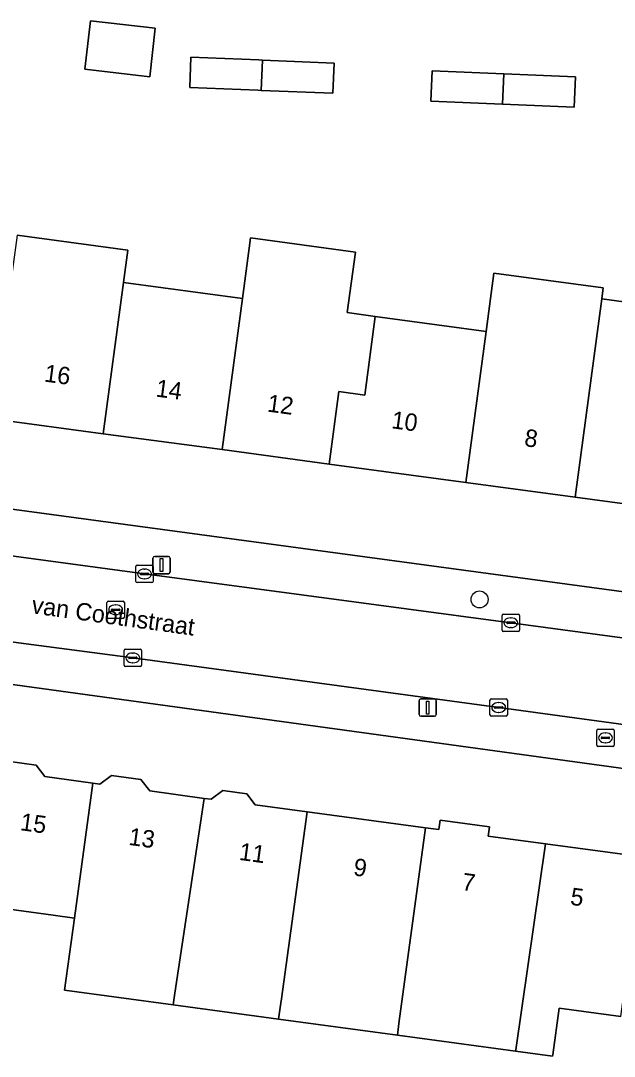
# Model space of a CAD drawing. Extents: x 161258 to 161838, y 380833 to 381727.
# Drawn here: x 161656.1 to 161690.3, y 381559.4 to 381619 of the extents above; entities that cross this region are included whole.
import ezdxf

# ---------------------------------------------------------------- set-up
doc = ezdxf.new("R2010")
doc.units = 0
for name, color, linetype in [('IMGEO_Boom', 7, 'Continuous'), ('IMGEO_Brandkraan', 7, 'Continuous'), ('IMGEO_Erf', 7, 'Continuous'), ('IMGEO_Kolk', 7, 'Continuous'), ('IMGEO_Lichtmast', 7, 'Continuous'), ('IMGEO_Openbare_ruimte_label', 7, 'Continuous'), ('IMGEO_Pand', 7, 'Continuous'), ('IMGEO_Pand_nummerreeks', 7, 'Continuous'), ('IMGEO_Rijbaan_lokaal_open', 7, 'Continuous'), ('IMGEO_Rioolput', 7, 'Continuous'), ('IMGEO_Voetpad_open', 7, 'Continuous')]:
    doc.layers.add(name, color=color, linetype=linetype)

msp = doc.modelspace()

# ---------------------------------------------------------------- linework, layer by layer
at = {"layer": 'IMGEO_Boom'}
msp.add_circle((161682.565, 381585.699), 0.489, dxfattribs=at)
at = {"layer": 'IMGEO_Brandkraan'}
for p, q in [((161689.314, 381577.311), (161689.314, 381578.163)), ((161689.389, 381578.237), (161690.241, 381578.237)), ((161689.573, 381577.731), (161689.573, 381577.743)), ((161689.616, 381577.78), (161690.014, 381577.78)), ((161689.802, 381578.017), (161689.827, 381578.017)), ((161690.057, 381577.743), (161690.057, 381577.731)), ((161690.315, 381578.163), (161690.315, 381577.311)), ((161690.241, 381577.237), (161689.389, 381577.237)), ((161690.011, 381577.694), (161689.613, 381577.694)), ((161689.825, 381577.457), (161689.8, 381577.457))]:
    msp.add_line(p, q, dxfattribs=at)
for points in [[(161689.314, 381577.311), (161689.314, 381578.163)], [(161689.389, 381578.237), (161690.241, 381578.237)], [(161690.315, 381578.163), (161690.315, 381577.311)], [(161690.241, 381577.237), (161689.389, 381577.237)]]:
    msp.add_lwpolyline(points, dxfattribs=at)
for centre, radius, start, end in [((161689.391, 381578.161), 0.0765, 91.55205, 178.44795), ((161689.391, 381578.161), 0.0765, 91.55205, 178.44795), ((161689.613, 381577.74), 0.0403, 85.87752, 175.75265), ((161689.61, 381577.73), 0.0366, 178.93798, 274.71019), ((161690.014, 381577.737), 0.043, 264.86636, 352.45326), ((161690.018, 381577.742), 0.0386, 1.73085, 96.63898), ((161690.239, 381578.161), 0.0765, 1.55205, 88.44795), ((161690.239, 381578.161), 0.0765, 1.55205, 88.44795), ((161689.391, 381577.313), 0.0765, 181.55205, 268.44795), ((161689.391, 381577.313), 0.0765, 181.55205, 268.44795), ((161690.239, 381577.313), 0.0765, 271.55205, 358.44795), ((161690.239, 381577.313), 0.0765, 271.55205, 358.44795)]:
    msp.add_arc(centre, radius, start, end, dxfattribs=at)
for centre, major_axis, ratio, start_param, end_param in [((161689.801, 381577.737), (-0.387, 0.002), 0.722429, 4.712389, 7.853982), ((161689.826, 381577.737), (-0.39, 0.002), 0.717154, 1.570796, 4.712389)]:
    msp.add_ellipse(centre, major_axis=major_axis, ratio=ratio, start_param=start_param, end_param=end_param, dxfattribs=at)
at = {"layer": 'IMGEO_Erf'}
for points in [[(161659.833, 381616.199), (161660.152, 381618.996), (161663.887, 381618.569), (161663.568, 381615.772)], [(161665.871, 381615.157), (161665.942, 381616.902), (161669.857, 381616.741), (161670.067, 381616.733), (161674.192, 381616.563), (161674.12, 381614.818), (161669.995, 381614.987), (161669.785, 381614.996)], [(161679.831, 381616.104), (161683.955, 381615.935), (161688.08, 381615.765), (161688.009, 381614.02), (161683.883, 381614.19), (161679.759, 381614.359)], [(161681.773, 381592.431), (161673.908, 381593.488), (161667.735, 381594.317), (161660.894, 381595.236), (161654.633, 381596.076), (161647.661, 381597.013), (161641.376, 381597.857), (161634.504, 381598.78), (161627.101, 381599.774), (161615.784, 381601.294), (161615.118, 381596.359), (161707.085, 381583.95), (161707.511, 381583.893), (161708.709, 381583.729), (161709.752, 381591.347), (161708.256, 381591.548), (161707.903, 381588.922), (161701.922, 381589.725), (161695.354, 381590.607), (161688.066, 381591.586)]]:
    msp.add_lwpolyline(points, close=True, dxfattribs=at)
for points in [[(161655.925, 381606.655), (161662.313, 381605.797), (161662.062, 381603.929), (161668.903, 381603.01), (161669.293, 381605.911), (161669.371, 381606.495), (161675.411, 381605.684), (161674.943, 381602.199), (161676.556, 381601.982), (161682.941, 381601.124), (161683.39, 381604.465), (161689.683, 381603.619), (161689.598, 381602.986), (161695.932, 381602.136)], [(161697.263, 381575.097), (161654.253, 381581.004)], [(161655.372, 381576.386), (161657.024, 381576.162), (161657.518, 381575.512), (161660.285, 381575.137), (161660.704, 381575.08), (161661.362, 381575.58), (161663.065, 381575.349), (161663.572, 381574.682), (161666.71, 381574.256), (161667.111, 381574.202), (161667.779, 381574.711), (161669.169, 381574.522), (161669.65, 381573.891), (161672.64, 381573.485), (161679.446, 381572.562), (161680.224, 381572.456), (161680.298, 381573.003), (161683.135, 381572.618), (161683.063, 381572.087), (161686.368, 381571.638), (161691.942, 381570.882)], [(161690.699, 381561.704), (161687.141, 381562.187), (161686.775, 381559.495), (161686.764, 381559.416), (161684.642, 381559.704), (161677.829, 381560.628), (161670.994, 381561.555), (161664.925, 381562.378), (161658.669, 381563.227), (161659.232, 381567.369), (161658.013, 381567.534), (161653.058, 381568.207)]]:
    msp.add_lwpolyline(points, dxfattribs=at)
at = {"layer": 'IMGEO_Kolk'}
for p, q in [((161662.765, 381586.74), (161662.765, 381587.592)), ((161662.84, 381587.666), (161663.692, 381587.666)), ((161663.253, 381587.446), (161663.278, 381587.446)), ((161663.766, 381587.592), (161663.766, 381586.74)), ((161663.692, 381586.666), (161662.84, 381586.666)), ((161663.024, 381587.16), (161663.024, 381587.172)), ((161663.462, 381587.123), (161663.064, 381587.123)), ((161663.067, 381587.209), (161663.465, 381587.209)), ((161663.276, 381586.886), (161663.251, 381586.886)), ((161663.508, 381587.172), (161663.508, 381587.16)), ((161683.867, 381583.933), (161683.867, 381584.785)), ((161683.942, 381584.859), (161684.794, 381584.859)), ((161684.126, 381584.353), (161684.126, 381584.365)), ((161684.564, 381584.316), (161684.166, 381584.316)), ((161684.169, 381584.402), (161684.567, 381584.402)), ((161684.355, 381584.639), (161684.38, 381584.639)), ((161684.61, 381584.365), (161684.61, 381584.353)), ((161684.868, 381584.785), (161684.868, 381583.933)), ((161684.794, 381583.859), (161683.942, 381583.859)), ((161684.378, 381584.079), (161684.353, 381584.079)), ((161662.093, 381581.911), (161662.093, 381582.763)), ((161662.168, 381582.837), (161663.02, 381582.837)), ((161662.581, 381582.617), (161662.606, 381582.617)), ((161663.094, 381582.763), (161663.094, 381581.911)), ((161662.352, 381582.331), (161662.352, 381582.343)), ((161662.79, 381582.294), (161662.392, 381582.294)), ((161662.395, 381582.38), (161662.793, 381582.38)), ((161662.604, 381582.057), (161662.579, 381582.057)), ((161662.836, 381582.343), (161662.836, 381582.331)), ((161663.02, 381581.837), (161662.168, 381581.837)), ((161683.164, 381579.056), (161683.164, 381579.908)), ((161683.239, 381579.982), (161684.091, 381579.982)), ((161683.466, 381579.525), (161683.864, 381579.525)), ((161683.652, 381579.762), (161683.677, 381579.762)), ((161684.165, 381579.908), (161684.165, 381579.056)), ((161684.091, 381578.982), (161683.239, 381578.982)), ((161683.423, 381579.476), (161683.423, 381579.488)), ((161683.861, 381579.439), (161683.463, 381579.439)), ((161683.675, 381579.202), (161683.65, 381579.202)), ((161683.907, 381579.488), (161683.907, 381579.476))]:
    msp.add_line(p, q, dxfattribs=at)
for points in [[(161662.765, 381586.74), (161662.765, 381587.592)], [(161662.84, 381587.666), (161663.692, 381587.666)], [(161663.766, 381587.592), (161663.766, 381586.74)], [(161663.692, 381586.666), (161662.84, 381586.666)], [(161683.867, 381583.933), (161683.867, 381584.785)], [(161683.942, 381584.859), (161684.794, 381584.859)], [(161684.868, 381584.785), (161684.868, 381583.933)], [(161684.794, 381583.859), (161683.942, 381583.859)], [(161662.093, 381581.911), (161662.093, 381582.763)], [(161662.168, 381582.837), (161663.02, 381582.837)], [(161663.094, 381582.763), (161663.094, 381581.911)], [(161663.02, 381581.837), (161662.168, 381581.837)], [(161683.164, 381579.056), (161683.164, 381579.908)], [(161683.239, 381579.982), (161684.091, 381579.982)], [(161684.165, 381579.908), (161684.165, 381579.056)], [(161684.091, 381578.982), (161683.239, 381578.982)]]:
    msp.add_lwpolyline(points, dxfattribs=at)
for centre, radius, start, end in [((161662.842, 381587.59), 0.0765, 91.55205, 178.44795), ((161662.842, 381587.59), 0.0765, 91.55205, 178.44795), ((161663.69, 381587.59), 0.0765, 1.55205, 88.44795), ((161663.69, 381587.59), 0.0765, 1.55205, 88.44795), ((161662.842, 381586.742), 0.0765, 181.55205, 268.44795), ((161662.842, 381586.742), 0.0765, 181.55205, 268.44795), ((161663.064, 381587.169), 0.0403, 85.87752, 175.75265), ((161663.061, 381587.159), 0.0366, 178.93798, 274.71019), ((161663.465, 381587.166), 0.043, 264.86636, 352.45326), ((161663.469, 381587.171), 0.0386, 1.73085, 96.63898), ((161663.69, 381586.742), 0.0765, 271.55205, 358.44795), ((161663.69, 381586.742), 0.0765, 271.55205, 358.44795), ((161683.944, 381584.783), 0.0765, 91.55205, 178.44795), ((161683.944, 381584.783), 0.0765, 91.55205, 178.44795), ((161684.166, 381584.362), 0.0403, 85.87752, 175.75265), ((161684.163, 381584.352), 0.0366, 178.93798, 274.71019), ((161684.567, 381584.359), 0.043, 264.86636, 352.45326), ((161684.571, 381584.364), 0.0386, 1.73085, 96.63898), ((161684.792, 381584.783), 0.0765, 1.55205, 88.44795), ((161684.792, 381584.783), 0.0765, 1.55205, 88.44795), ((161683.944, 381583.935), 0.0765, 181.55205, 268.44795), ((161683.944, 381583.935), 0.0765, 181.55205, 268.44795), ((161684.792, 381583.935), 0.0765, 271.55205, 358.44795), ((161684.792, 381583.935), 0.0765, 271.55205, 358.44795), ((161662.17, 381582.761), 0.0765, 91.55205, 178.44795), ((161662.17, 381582.761), 0.0765, 91.55205, 178.44795), ((161663.018, 381582.761), 0.0765, 1.55205, 88.44795), ((161663.018, 381582.761), 0.0765, 1.55205, 88.44795), ((161662.17, 381581.913), 0.0765, 181.55205, 268.44795), ((161662.17, 381581.913), 0.0765, 181.55205, 268.44795), ((161662.392, 381582.34), 0.0403, 85.87752, 175.75265), ((161662.389, 381582.33), 0.0366, 178.93798, 274.71019), ((161662.793, 381582.337), 0.043, 264.86636, 352.45326), ((161662.797, 381582.342), 0.0386, 1.73085, 96.63898), ((161663.018, 381581.913), 0.0765, 271.55205, 358.44795), ((161663.018, 381581.913), 0.0765, 271.55205, 358.44795), ((161683.241, 381579.906), 0.0765, 91.55205, 178.44795), ((161683.241, 381579.906), 0.0765, 91.55205, 178.44795), ((161683.463, 381579.485), 0.0403, 85.87752, 175.75265), ((161683.868, 381579.487), 0.0386, 1.73085, 96.63898), ((161684.089, 381579.906), 0.0765, 1.55205, 88.44795), ((161684.089, 381579.906), 0.0765, 1.55205, 88.44795), ((161683.241, 381579.058), 0.0765, 181.55205, 268.44795), ((161683.241, 381579.058), 0.0765, 181.55205, 268.44795), ((161683.46, 381579.475), 0.0366, 178.93798, 274.71019), ((161683.864, 381579.482), 0.043, 264.86636, 352.45326), ((161684.089, 381579.058), 0.0765, 271.55205, 358.44795), ((161684.089, 381579.058), 0.0765, 271.55205, 358.44795)]:
    msp.add_arc(centre, radius, start, end, dxfattribs=at)
for centre, major_axis, ratio, start_param, end_param in [((161663.252, 381587.166), (-0.387, 0.002), 0.722429, 4.712389, 7.853982), ((161663.277, 381587.166), (-0.39, 0.002), 0.717154, 1.570796, 4.712389), ((161684.354, 381584.359), (-0.387, 0.002), 0.722429, 4.712389, 7.853982), ((161684.379, 381584.359), (-0.39, 0.002), 0.717154, 1.570796, 4.712389), ((161662.58, 381582.337), (-0.387, 0.002), 0.722429, 4.712389, 7.853982), ((161662.605, 381582.337), (-0.39, 0.002), 0.717154, 1.570796, 4.712389), ((161683.651, 381579.482), (-0.387, 0.002), 0.722429, 4.712389, 7.853982), ((161683.676, 381579.482), (-0.39, 0.002), 0.717154, 1.570796, 4.712389)]:
    msp.add_ellipse(centre, major_axis=major_axis, ratio=ratio, start_param=start_param, end_param=end_param, dxfattribs=at)
at = {"layer": 'IMGEO_Lichtmast'}
for p, q in [((161663.754, 381587.277), (161663.754, 381588.077)), ((161663.754, 381588.077), (161663.754, 381587.277)), ((161663.854, 381588.177), (161664.644, 381588.177)), ((161664.644, 381588.177), (161663.854, 381588.177)), ((161664.744, 381588.077), (161664.744, 381587.277)), ((161664.744, 381587.277), (161664.744, 381588.077)), ((161664.644, 381587.177), (161663.854, 381587.177)), ((161663.854, 381587.177), (161664.644, 381587.177)), ((161679.08, 381579.08), (161679.08, 381579.88)), ((161679.08, 381579.88), (161679.08, 381579.08)), ((161679.18, 381579.98), (161679.97, 381579.98)), ((161679.97, 381579.98), (161679.18, 381579.98)), ((161680.07, 381579.88), (161680.07, 381579.08)), ((161680.07, 381579.08), (161680.07, 381579.88)), ((161679.97, 381578.98), (161679.18, 381578.98)), ((161679.18, 381578.98), (161679.97, 381578.98))]:
    msp.add_line(p, q, dxfattribs=at)
for points in [[(161664.174, 381588.052), (161664.324, 381588.052), (161664.324, 381587.302), (161664.174, 381587.302), (161664.174, 381588.052)], [(161679.5, 381579.855), (161679.65, 381579.855), (161679.65, 381579.105), (161679.5, 381579.105), (161679.5, 381579.855)]]:
    msp.add_lwpolyline(points, dxfattribs=at)
for centre, start, end in [((161663.854, 381588.077), 90, 180), ((161663.854, 381588.077), 90, 180), ((161664.644, 381588.077), 0, 90), ((161664.644, 381588.077), 360, 90), ((161663.854, 381587.277), 180, 270), ((161663.854, 381587.277), 180, 270), ((161664.644, 381587.277), 270, 0), ((161664.644, 381587.277), 270, 0), ((161679.18, 381579.88), 90, 180), ((161679.18, 381579.88), 90, 180), ((161679.97, 381579.88), 0, 90), ((161679.97, 381579.88), 360, 90), ((161679.18, 381579.08), 180, 270), ((161679.18, 381579.08), 180, 270), ((161679.97, 381579.08), 270, 0), ((161679.97, 381579.08), 270, 0)]:
    msp.add_arc(centre, 0.1, start, end, dxfattribs=at)
at = {"layer": 'IMGEO_Pand'}
for points in [[(161659.833, 381616.199), (161663.568, 381615.772), (161663.887, 381618.569), (161660.152, 381618.996)], [(161670.067, 381616.733), (161669.857, 381616.741), (161665.942, 381616.902), (161665.871, 381615.157), (161669.785, 381614.996), (161669.995, 381614.987)], [(161670.067, 381616.733), (161669.995, 381614.987), (161674.12, 381614.818), (161674.192, 381616.563)], [(161683.883, 381614.19), (161683.955, 381615.935), (161679.831, 381616.104), (161679.759, 381614.359)], [(161683.883, 381614.19), (161688.009, 381614.02), (161688.08, 381615.765), (161683.955, 381615.935)], [(161662.062, 381603.929), (161662.313, 381605.797), (161655.925, 381606.655), (161655.452, 381603.137), (161654.633, 381596.076), (161660.894, 381595.236)], [(161676.556, 381601.982), (161674.943, 381602.199), (161675.411, 381605.684), (161669.371, 381606.495), (161669.293, 381605.911), (161668.903, 381603.01), (161667.735, 381594.317), (161673.908, 381593.488), (161674.468, 381597.658), (161675.948, 381597.459)], [(161689.598, 381602.986), (161689.683, 381603.619), (161683.39, 381604.465), (161682.941, 381601.124), (161681.773, 381592.431), (161688.066, 381591.586)], [(161667.735, 381594.317), (161668.903, 381603.01), (161662.062, 381603.929), (161660.894, 381595.236)], [(161689.598, 381602.986), (161688.066, 381591.586), (161695.354, 381590.607), (161696.469, 381598.902), (161695.514, 381599.03), (161695.932, 381602.136)], [(161673.908, 381593.488), (161681.773, 381592.431), (161682.941, 381601.124), (161676.556, 381601.982), (161675.948, 381597.459), (161674.468, 381597.658)], [(161660.285, 381575.137), (161657.518, 381575.512), (161657.024, 381576.162), (161655.372, 381576.386), (161654.757, 381575.918), (161654.116, 381576.004), (161653.058, 381568.207), (161658.013, 381567.534), (161659.232, 381567.369)], [(161665.017, 381563.053), (161666.71, 381574.256), (161663.572, 381574.682), (161663.065, 381575.349), (161661.362, 381575.58), (161660.704, 381575.08), (161660.285, 381575.137), (161659.232, 381567.369), (161658.669, 381563.227), (161664.925, 381562.378)], [(161672.64, 381573.485), (161669.65, 381573.891), (161669.169, 381574.522), (161667.779, 381574.711), (161667.111, 381574.202), (161666.71, 381574.256), (161665.017, 381563.053), (161664.925, 381562.378), (161670.994, 381561.555), (161671.088, 381562.229), (161671.156, 381562.73)], [(161679.446, 381572.562), (161672.64, 381573.485), (161671.156, 381562.73), (161671.088, 381562.229), (161670.994, 381561.555), (161677.829, 381560.628), (161677.92, 381561.301)], [(161686.368, 381571.638), (161683.063, 381572.087), (161683.135, 381572.618), (161680.298, 381573.003), (161680.224, 381572.456), (161679.446, 381572.562), (161677.92, 381561.301), (161677.829, 381560.628), (161684.642, 381559.704), (161684.653, 381559.783)], [(161691.942, 381570.882), (161686.368, 381571.638), (161684.653, 381559.783), (161684.642, 381559.704), (161686.764, 381559.416), (161686.775, 381559.495), (161687.141, 381562.187), (161690.699, 381561.704)]]:
    msp.add_lwpolyline(points, close=True, dxfattribs=at)
at = {"layer": 'IMGEO_Rijbaan_lokaal_open'}
for points in [[(161723.791, 381579.08), (161713.619, 381580.431), (161707.156, 381581.295), (161706.756, 381581.348), (161684.368, 381584.359), (161663.266, 381587.166), (161645.071, 381589.627), (161619.675, 381593.074), (161618.458, 381593.224), (161618.426, 381593.228), (161614.689, 381593.717), (161591.61, 381596.833)], [(161591.008, 381591.931), (161614.153, 381588.812), (161617.916, 381588.319), (161619.122, 381588.157), (161644.429, 381584.771), (161646.629, 381584.448), (161656.447, 381583.147), (161662.594, 381582.337), (161683.665, 381579.482), (161697.6, 381577.592), (161697.62, 381577.589), (161697.936, 381577.548), (161704.805, 381576.659), (161705.23, 381576.604), (161705.253, 381576.601), (161706.214, 381576.473), (161723.234, 381574.173)]]:
    msp.add_lwpolyline(points, dxfattribs=at)
at = {"layer": 'IMGEO_Rioolput'}
for p, q in [((161661.107, 381584.68), (161661.107, 381585.532)), ((161661.182, 381585.606), (161662.034, 381585.606)), ((161662.108, 381585.532), (161662.108, 381584.68)), ((161661.366, 381585.1), (161661.366, 381585.112)), ((161661.804, 381585.063), (161661.406, 381585.063)), ((161661.409, 381585.149), (161661.807, 381585.149)), ((161661.595, 381585.386), (161661.62, 381585.386)), ((161661.85, 381585.112), (161661.85, 381585.1)), ((161662.034, 381584.606), (161661.182, 381584.606)), ((161661.618, 381584.826), (161661.593, 381584.826))]:
    msp.add_line(p, q, dxfattribs=at)
for points in [[(161661.107, 381584.68), (161661.107, 381585.532)], [(161661.182, 381585.606), (161662.034, 381585.606)], [(161662.108, 381585.532), (161662.108, 381584.68)], [(161662.034, 381584.606), (161661.182, 381584.606)]]:
    msp.add_lwpolyline(points, dxfattribs=at)
for centre, radius, start, end in [((161661.184, 381585.53), 0.0765, 91.55205, 178.44795), ((161661.184, 381585.53), 0.0765, 91.55205, 178.44795), ((161662.032, 381585.53), 0.0765, 1.55205, 88.44795), ((161662.032, 381585.53), 0.0765, 1.55205, 88.44795), ((161661.406, 381585.109), 0.0403, 85.87752, 175.75265), ((161661.403, 381585.099), 0.0366, 178.93798, 274.71019), ((161661.807, 381585.106), 0.043, 264.86636, 352.45326), ((161661.811, 381585.111), 0.0386, 1.73085, 96.63898), ((161661.184, 381584.682), 0.0765, 181.55205, 268.44795), ((161661.184, 381584.682), 0.0765, 181.55205, 268.44795), ((161662.032, 381584.682), 0.0765, 271.55205, 358.44795), ((161662.032, 381584.682), 0.0765, 271.55205, 358.44795)]:
    msp.add_arc(centre, radius, start, end, dxfattribs=at)
for centre, major_axis, ratio, start_param, end_param in [((161661.594, 381585.106), (-0.387, 0.002), 0.722429, 4.712389, 7.853982), ((161661.619, 381585.106), (-0.39, 0.002), 0.717154, 1.570796, 4.712389)]:
    msp.add_ellipse(centre, major_axis=major_axis, ratio=ratio, start_param=start_param, end_param=end_param, dxfattribs=at)
at = {"layer": 'IMGEO_Voetpad_open'}
msp.add_lwpolyline([(161615.118, 381596.359), (161613.919, 381596.521), (161590.17, 381599.725), (161590.41, 381597.026), (161590.506, 381597.003), (161590.603, 381596.979), (161591.3, 381596.865), (161591.61, 381596.833), (161614.689, 381593.717), (161618.426, 381593.228), (161618.458, 381593.224), (161619.675, 381593.074), (161645.071, 381589.627), (161663.266, 381587.166), (161684.368, 381584.359), (161706.756, 381581.348), (161707.156, 381581.295), (161707.511, 381583.893), (161707.085, 381583.95)], close=True, dxfattribs=at)
msp.add_lwpolyline([(161589.258, 381589.545), (161648.507, 381581.81), (161648.68, 381581.562), (161654.227, 381580.806), (161654.253, 381581.004), (161697.263, 381575.097), (161697.567, 381575.055), (161697.936, 381577.548), (161697.62, 381577.589), (161697.6, 381577.592), (161683.665, 381579.482), (161662.594, 381582.337), (161656.447, 381583.147), (161646.629, 381584.448)], dxfattribs=at)

# ---------------------------------------------------------------- texts
at = {"layer": 'IMGEO_Openbare_ruimte_label'}
msp.add_text('van Coothstraat', height=1, rotation=352.12908, dxfattribs=at).set_placement((161656.726, 381584.909))
at = {"layer": 'IMGEO_Pand_nummerreeks'}
for s, rotation, p in [('16', 352.35101, (161657.454, 381598.24)), ('14', 352.35069, (161663.877, 381597.378)), ('12', 352.35101, (161670.3, 381596.514)), ('10', 352.35069, (161677.449, 381595.555)), ('8', 352.35069, (161685.106, 381594.527)), ('15', 352.28589, (161656.07, 381572.429)), ('13', 352.28589, (161662.315, 381571.583)), ('11', 352.28799, (161668.674, 381570.721)), ('9', 352.28799, (161675.262, 381569.829)), ('7', 352.28799, (161681.508, 381568.983)), ('5', 352.28799, (161687.753, 381568.137))]:
    msp.add_text(s, height=1, rotation=rotation, dxfattribs=at).set_placement(p)

doc.saveas('drawing.dxf')
